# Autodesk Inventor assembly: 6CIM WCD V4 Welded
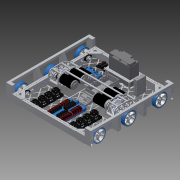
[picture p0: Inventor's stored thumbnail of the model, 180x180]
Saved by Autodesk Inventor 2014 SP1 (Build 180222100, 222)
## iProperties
Created: 2014-09
Part Number: 6CIM WCD V4 Welded
Document SubType Name: Assembly
Designer: Michael
Mass: 17694.5 g
Surface Area: 46905.3 cm^2
Volume: 10866 cm^3
Density: 1.62843 g/cm^3
Author: Michael
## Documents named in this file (25)
- C:\Users\Michael\Documents\Inventor\6 CIM in Line\6CIM WCD V4 Welded.iam
- C:\Users\Michael\Documents\Inventor\6 CIM V2\Base Plate.ipt
- C:\Users\Michael\Documents\Inventor\6 CIM V2\Side Rail.ipt
- C:\Users\Michael\Documents\Inventor\6 CIM V2\Front and Back Rail.ipt
- C:\Users\Michael\Documents\Inventor\6 CIM V2\Wheel-Bearing Block-Sprocket Sub.iam
- C:\Users\Michael\Documents\Inventor\6 CIM V2\Middle Wheel-Bearing Block.iam
- C:\Users\Michael\Documents\Inventor\6 CIM V2\217-3431-STEP.ipt
- C:\Users\Michael\Documents\Inventor\6 CIM V2\Battery Box.ipt
- C:\Users\Michael\Documents\Inventor\6 CIM V2\CS_Controller_217-2769.ipt
- C:\Users\Michael\Documents\Inventor\6 CIM V2\CS_PowerBoard_A003206.ipt
- C:\Users\Michael\Documents\Inventor\Bicycle\Imported Components\cd_crio-9074\cd_crio-9074.ipt
- C:\Users\Michael\Documents\Inventor\6 CIM V2\CS_SideCar_A003333.ipt
- C:\Users\Michael\Documents\Inventor\6 CIM V2\Breaker.iam
- C:\Users\Michael\Documents\Inventor\6 CIM V2\EK_6_Port_Manifold.ipt
- C:\Users\Michael\Documents\Inventor\6 CIM V2\battery.ipt
- C:\Users\Michael\Documents\Inventor\6 CIM V2\Battery Box Standoff.ipt
- C:\Users\Michael\Documents\Inventor\6 CIM V2\Gearbox Connecting Standoff.ipt
- C:\Users\Michael\Documents\Inventor\6 CIM in Line\6 CIM in Line Gearbox Ratio 2.iam
- C:\Users\Michael\Documents\Inventor\6 CIM in Line\6 CIM in Line Gearbox Ratio 2 MIR.ipt
- C:\Users\Michael\Documents\Inventor\6CIM\Wheel Well Frame Block.ipt
- C:\Users\Michael\Documents\Inventor\6CIM\Frame Mounting Bar.ipt
- C:\Users\Michael\Documents\Inventor\6CIM\Frame Mounting Corner.ipt
- C:\Users\Michael\Documents\Inventor\6CIM\Frame Mounting Corner Cap.ipt
- C:\Users\Michael\Documents\Inventor\6CIM\Wheel Well Frame Block Cap.ipt
- C:\Users\Michael\Documents\Inventor\6 CIM V2\Gusset.ipt
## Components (58 placed, 24 different names)
1. Base Plate:1 — Mate:1, Mate:2, Mate:3, Mate:4, Mate:5, Mate:6, Mate:8, Mate:9, Mate:10, Mate:11, Mate:71, Mate:75, Mate:76, Mate:92, Mate:94, Mate:97, Mate:99, Mate:106, Mate:119, Mate:152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
2. Side Rail:1 — Mate:1, Flush:1, Mate:2, Mate:3, Mate:27, Mate:28, Mate:29, Mate:30, Mate:31, Mate:32, Mate:33, Mate:34, Mate:35, Mate:45, Mate:46, Mate:47, Mate:48, Mate:79, Angle:1, Mate:111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
3. Side Rail:2 — Flush:1, Mate:4, Mate:5, Mate:7, Mate:21, Mate:22, Mate:23, Mate:24, Mate:25, Mate:26, Mate:36, Mate:37, Mate:38, Mate:43, Mate:44, Mate:49, Mate:50, Angle:2, Mate:102, Mate:153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
4. Front and Back Rail:1 — Mate:9, Mate:10, Mate:11, Mate:70, Mate:74, Mate:112, Mate:172, Mate:175, Mate:178, Mate:181, Flush:97, Flush:98, Mate:182, Flush:99, Flush:100, Mate:197, Flush:116, Mate:198, Flush:117
5. Front and Back Rail:2 — Mate:6, Mate:7, Mate:8, Mate:83, Mate:95, Mate:171, Mate:176, Mate:179, Flush:91, Flush:92, Flush:93, Flush:94, Mate:180, Flush:95, Flush:96, Mate:196, Flush:113, Mate:199, Flush:119
6. Wheel-Bearing Block-Sprocket Sub:1 [sub-assembly] — Mate:27, Mate:28, Mate:29
7. Wheel-Bearing Block-Sprocket Sub:2 [sub-assembly] — Mate:30, Mate:31, Mate:32
8. Wheel-Bearing Block-Sprocket Sub:3 [sub-assembly] — Mate:21, Mate:22, Mate:23
9. Wheel-Bearing Block-Sprocket Sub:4 [sub-assembly] — Mate:24, Mate:25, Mate:26
10. Middle Wheel-Bearing Block:1 [sub-assembly] — Mate:33, Mate:34, Mate:35
11. Middle Wheel-Bearing Block:2 [sub-assembly] — Mate:36, Mate:37, Mate:38, Tangent:1, Tangent:2
12. 217-3431-STEP:1 — Mate:44, Mate:49
13. 217-3431-STEP:2 — Mate:45, Mate:48
14. 217-3431-STEP:3 — Mate:43, Mate:50
15. 217-3431-STEP:4 — Mate:46, Mate:47
16. Battery Box:1 — Mate:70, Flush:14, Mate:74, Mate:105, Mate:108, Mate:110, Mate:151, Mate:167, Mate:168
17. CS_Controller_217-2769:1 — Mate:75, Mate:79, Flush:15, Flush:18, Mate:80, Mate:83, Flush:82
18. CS_Controller_217-2769:2 — Mate:76, Flush:21, Flush:79
19. CS_Controller_217-2769:3 — Flush:15, Flush:16, Flush:18, Flush:19, Mate:80, Mate:81, Flush:81
20. CS_Controller_217-2769:4 — Flush:16, Flush:17, Flush:19, Flush:20, Mate:81, Mate:82, Flush:80
21. CS_Controller_217-2769:5 — Flush:17, Flush:20, Mate:82, Flush:79
22. CS_Controller_217-2769:6 — Flush:21, Flush:22, Flush:80
23. CS_Controller_217-2769:7 — Flush:22, Flush:23, Flush:81
24. CS_Controller_217-2769:8 — Flush:23, Flush:82
25. CS_PowerBoard_A003206:1 — Mate:92, Angle:1, Mate:93, Mate:95
26. cd_crio-9074:1 — Mate:94, Flush:24, Mate:166
27. CS_SideCar_A003333:1 — Mate:97, Mate:156
28. Breaker:1 [sub-assembly] — Mate:99, Angle:2, Mate:102, Mate:164
29. EK_6_Port_Manifold:1 — Mate:106, Mate:111, Mate:112
30. battery:1 — Mate:105, Mate:151, Mate:152
31. Battery Box Standoff:1 — Mate:108, Mate:168
32. Battery Box Standoff:4 — Mate:110, Mate:167
33. Gearbox Connecting Standoff:1 — Mate:162, Mate:163
34. Gearbox Connecting Standoff:2 — Mate:160, Mate:161
35. 6 CIM in Line Gearbox Ratio 2:1 [sub-assembly] — Mate:153, Mate:154, Mate:155, Mate:161, Mate:162, Mate:163
36. 6 CIM in Line Gearbox Ratio 2 MIR:1 — Mate:157, Mate:158, Mate:159, Mate:160
37. Wheel Well Frame Block:1 — Flush:84, Mate:170, Mate:171, Mate:190, Flush:110
38. Wheel Well Frame Block:2 — Mate:169, Flush:83, Mate:172, Flush:90, Mate:188, Flush:109
39. Wheel Well Frame Block:3 — Flush:86, Mate:174, Mate:176, Flush:111
40. Wheel Well Frame Block:4 — Mate:173, Flush:85, Mate:175, Flush:87, Mate:194, Flush:112
41. Frame Mounting Bar:1 — Flush:87, Mate:178, Flush:88, Flush:89, Flush:108, Mate:193, Mate:195
42. Frame Mounting Bar:2 — Flush:88, Flush:89, Flush:90, Mate:184, Mate:189, Mate:191
43. Frame Mounting Corner:1 — Mate:182, Flush:99, Flush:100, Mate:187, Flush:106, Flush:107
44. Frame Mounting Corner:2 — Mate:179, Flush:91, Flush:92, Flush:93, Flush:94, Mate:186, Flush:104, Flush:105
45. Frame Mounting Corner:3 — Mate:180, Flush:95, Flush:96, Mate:185, Flush:102, Flush:103
46. Frame Mounting Corner:4 — Mate:181, Flush:97, Flush:98, Mate:183, Flush:101
47. Frame Mounting Corner Cap:1 — Mate:183, Mate:184, Flush:101
48. Frame Mounting Corner Cap:2 — Mate:187, Flush:106, Flush:107, Flush:108
49. Frame Mounting Corner Cap:3 — Mate:185, Flush:102, Flush:103
50. Frame Mounting Corner Cap:4 — Mate:186, Flush:104, Flush:105
51. Wheel Well Frame Block Cap:1 — Mate:190, Mate:191, Flush:110
52. Wheel Well Frame Block Cap:2 — Mate:194, Mate:195, Flush:112
53. Wheel Well Frame Block Cap:3 — Mate:188, Mate:189, Flush:109
54. Wheel Well Frame Block Cap:4 — Mate:192, Mate:193, Flush:111
55. Gusset:1 — Mate:199, Flush:119, Flush:120
56. Gusset:2 — Mate:197, Flush:115, Flush:116
57. Gusset:3 — Mate:196, Flush:113, Flush:114
58. Gusset:4 — Mate:198, Flush:117, Flush:118
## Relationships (167: Mate 108, Flush 54, Angle 3, Tangent 2)
- Mate:1: Base Plate:1 ↔ Side Rail:1
- Flush:1: Side Rail:1 ↔ Side Rail:2
- Mate:2: Base Plate:1 ↔ Side Rail:1
- Mate:3: Base Plate:1 ↔ Side Rail:1
- Mate:4: Base Plate:1 ↔ Side Rail:2
- Mate:5: Base Plate:1 ↔ Side Rail:2
- Mate:6: Base Plate:1 ↔ Front and Back Rail:2
- Mate:7: Side Rail:2 ↔ Front and Back Rail:2
- Mate:8: Base Plate:1 ↔ Front and Back Rail:2
- Mate:9: Base Plate:1 ↔ Front and Back Rail:1
- Mate:10: Base Plate:1 ↔ Front and Back Rail:1
- Mate:11: Base Plate:1 ↔ Front and Back Rail:1
- Mate:21: Side Rail:2 ↔ Wheel-Bearing Block-Sprocket Sub:3
- Mate:22: Side Rail:2 ↔ Wheel-Bearing Block-Sprocket Sub:3
- Mate:23: Side Rail:2 ↔ Wheel-Bearing Block-Sprocket Sub:3
- Mate:24: Side Rail:2 ↔ Wheel-Bearing Block-Sprocket Sub:4
- Mate:25: Side Rail:2 ↔ Wheel-Bearing Block-Sprocket Sub:4
- Mate:26: Side Rail:2 ↔ Wheel-Bearing Block-Sprocket Sub:4
- Mate:27: Side Rail:1 ↔ Wheel-Bearing Block-Sprocket Sub:1
- Mate:28: Side Rail:1 ↔ Wheel-Bearing Block-Sprocket Sub:1
- Mate:29: Side Rail:1 ↔ Wheel-Bearing Block-Sprocket Sub:1
- Mate:30: Side Rail:1 ↔ Wheel-Bearing Block-Sprocket Sub:2
- Mate:31: Side Rail:1 ↔ Wheel-Bearing Block-Sprocket Sub:2
- Mate:32: Side Rail:1 ↔ Wheel-Bearing Block-Sprocket Sub:2
- Mate:33: Side Rail:1 ↔ Middle Wheel-Bearing Block:1
- Mate:34: Side Rail:1 ↔ Middle Wheel-Bearing Block:1
- Mate:35: Side Rail:1 ↔ Middle Wheel-Bearing Block:1
- Mate:36: Side Rail:2 ↔ Middle Wheel-Bearing Block:2
- Mate:37: Side Rail:2 ↔ Middle Wheel-Bearing Block:2
- Mate:38: Side Rail:2 ↔ Middle Wheel-Bearing Block:2
- Mate:43: Side Rail:2 ↔ 217-3431-STEP:3
- Mate:44: Side Rail:2 ↔ 217-3431-STEP:1
- Mate:45: Side Rail:1 ↔ 217-3431-STEP:2
- Mate:46: Side Rail:1 ↔ 217-3431-STEP:4
- Mate:47: Side Rail:1 ↔ 217-3431-STEP:4
- Mate:48: Side Rail:1 ↔ 217-3431-STEP:2
- Mate:49: Side Rail:2 ↔ 217-3431-STEP:1
- Mate:50: Side Rail:2 ↔ 217-3431-STEP:3
- Mate:70: Front and Back Rail:1 ↔ Battery Box:1
- Mate:71: Base Plate:1
- Flush:14: Battery Box:1
- Mate:74: Front and Back Rail:1 ↔ Battery Box:1
- Mate:75: Base Plate:1 ↔ CS_Controller_217-2769:1
- Mate:76: Base Plate:1 ↔ CS_Controller_217-2769:2
- Mate:79: Side Rail:1 ↔ CS_Controller_217-2769:1
- Flush:15: CS_Controller_217-2769:1 ↔ CS_Controller_217-2769:3
- Flush:16: CS_Controller_217-2769:3 ↔ CS_Controller_217-2769:4
- Flush:17: CS_Controller_217-2769:4 ↔ CS_Controller_217-2769:5
- Flush:18: CS_Controller_217-2769:1 ↔ CS_Controller_217-2769:3
- Flush:19: CS_Controller_217-2769:3 ↔ CS_Controller_217-2769:4
- Flush:20: CS_Controller_217-2769:4 ↔ CS_Controller_217-2769:5
- Mate:80: CS_Controller_217-2769:1 ↔ CS_Controller_217-2769:3
- Mate:81: CS_Controller_217-2769:3 ↔ CS_Controller_217-2769:4
- Mate:82: CS_Controller_217-2769:4 ↔ CS_Controller_217-2769:5
- Mate:83: Front and Back Rail:2 ↔ CS_Controller_217-2769:1
- Flush:21: CS_Controller_217-2769:2 ↔ CS_Controller_217-2769:6
- Flush:22: CS_Controller_217-2769:6 ↔ CS_Controller_217-2769:7
- Flush:23: CS_Controller_217-2769:7 ↔ CS_Controller_217-2769:8
- Mate:92: Base Plate:1 ↔ CS_PowerBoard_A003206:1
- Angle:1: Side Rail:1 ↔ CS_PowerBoard_A003206:1
- Mate:93: CS_PowerBoard_A003206:1
- Mate:94: Base Plate:1 ↔ cd_crio-9074:1
- Flush:24: cd_crio-9074:1
- Mate:95: Front and Back Rail:2 ↔ CS_PowerBoard_A003206:1
- Mate:97: Base Plate:1 ↔ CS_SideCar_A003333:1
- Mate:99: Base Plate:1 ↔ Breaker:1
- Angle:2: Side Rail:2 ↔ Breaker:1
- Mate:102: Side Rail:2 ↔ Breaker:1
- Mate:105: Battery Box:1 ↔ battery:1
- Mate:106: Base Plate:1 ↔ EK_6_Port_Manifold:1
- Mate:108: Battery Box:1 ↔ Battery Box Standoff:1
- Mate:110: Battery Box:1 ↔ Battery Box Standoff:4
- Mate:111: Side Rail:1 ↔ EK_6_Port_Manifold:1
- Mate:112: Front and Back Rail:1 ↔ EK_6_Port_Manifold:1
- Tangent:1: Middle Wheel-Bearing Block:2
- Mate:119: Base Plate:1
- Mate:151: Battery Box:1 ↔ battery:1
- Mate:152: Base Plate:1 ↔ battery:1
- Mate:153: Side Rail:2 ↔ 6 CIM in Line Gearbox Ratio 2:1
- Mate:154: Side Rail:2 ↔ 6 CIM in Line Gearbox Ratio 2:1
- Mate:155: Side Rail:2 ↔ 6 CIM in Line Gearbox Ratio 2:1
- Mate:156: Base Plate:1 ↔ CS_SideCar_A003333:1
- Mate:157: Side Rail:1 ↔ 6 CIM in Line Gearbox Ratio 2 MIR:1
- Mate:158: Side Rail:1 ↔ 6 CIM in Line Gearbox Ratio 2 MIR:1
- Mate:159: Side Rail:1 ↔ 6 CIM in Line Gearbox Ratio 2 MIR:1
- Mate:160: Gearbox Connecting Standoff:2 ↔ 6 CIM in Line Gearbox Ratio 2 MIR:1
- Mate:161: Gearbox Connecting Standoff:2 ↔ 6 CIM in Line Gearbox Ratio 2:1
- Mate:162: Gearbox Connecting Standoff:1 ↔ 6 CIM in Line Gearbox Ratio 2:1
- Mate:163: Gearbox Connecting Standoff:1 ↔ 6 CIM in Line Gearbox Ratio 2:1
- Angle:4: Side Rail:2
- Tangent:2: Middle Wheel-Bearing Block:2
- Mate:164: Base Plate:1 ↔ Breaker:1
- Mate:166: Base Plate:1 ↔ cd_crio-9074:1
- Mate:167: Battery Box:1 ↔ Battery Box Standoff:4
- Mate:168: Battery Box:1 ↔ Battery Box Standoff:1
- Flush:79: CS_Controller_217-2769:2 ↔ CS_Controller_217-2769:5
- Flush:80: CS_Controller_217-2769:4 ↔ CS_Controller_217-2769:6
- Flush:81: CS_Controller_217-2769:3 ↔ CS_Controller_217-2769:7
- Flush:82: CS_Controller_217-2769:1 ↔ CS_Controller_217-2769:8
- Mate:169: Side Rail:2 ↔ Wheel Well Frame Block:2
- Flush:83: Side Rail:2 ↔ Wheel Well Frame Block:2
- Flush:84: Side Rail:2 ↔ Wheel Well Frame Block:1
- Mate:170: Side Rail:2 ↔ Wheel Well Frame Block:1
- Mate:171: Front and Back Rail:2 ↔ Wheel Well Frame Block:1
- Mate:172: Front and Back Rail:1 ↔ Wheel Well Frame Block:2
- Mate:173: Side Rail:1 ↔ Wheel Well Frame Block:4
- Flush:85: Side Rail:1 ↔ Wheel Well Frame Block:4
- Flush:86: Side Rail:1 ↔ Wheel Well Frame Block:3
- Mate:174: Side Rail:1 ↔ Wheel Well Frame Block:3
- Mate:175: Front and Back Rail:1 ↔ Wheel Well Frame Block:4
- Mate:176: Front and Back Rail:2 ↔ Wheel Well Frame Block:3
- Flush:87: Wheel Well Frame Block:4 ↔ Frame Mounting Bar:1
- Mate:178: Front and Back Rail:1 ↔ Frame Mounting Bar:1
- Flush:88: Frame Mounting Bar:1 ↔ Frame Mounting Bar:2
- Flush:89: Frame Mounting Bar:1 ↔ Frame Mounting Bar:2
- Flush:90: Wheel Well Frame Block:2 ↔ Frame Mounting Bar:2
- Mate:179: Front and Back Rail:2 ↔ Frame Mounting Corner:2
- Flush:91: Front and Back Rail:2 ↔ Frame Mounting Corner:2
- Flush:92: Front and Back Rail:2 ↔ Frame Mounting Corner:2
- Flush:93: Front and Back Rail:2 ↔ Frame Mounting Corner:2
- Flush:94: Front and Back Rail:2 ↔ Frame Mounting Corner:2
- Mate:180: Front and Back Rail:2 ↔ Frame Mounting Corner:3
- Flush:95: Front and Back Rail:2 ↔ Frame Mounting Corner:3
- Flush:96: Front and Back Rail:2 ↔ Frame Mounting Corner:3
- Mate:181: Front and Back Rail:1 ↔ Frame Mounting Corner:4
- Flush:97: Front and Back Rail:1 ↔ Frame Mounting Corner:4
- Flush:98: Front and Back Rail:1 ↔ Frame Mounting Corner:4
- Mate:182: Front and Back Rail:1 ↔ Frame Mounting Corner:1
- Flush:99: Front and Back Rail:1 ↔ Frame Mounting Corner:1
- Flush:100: Front and Back Rail:1 ↔ Frame Mounting Corner:1
- Mate:183: Frame Mounting Corner:4 ↔ Frame Mounting Corner Cap:1
- Mate:184: Frame Mounting Bar:2 ↔ Frame Mounting Corner Cap:1
- Flush:101: Frame Mounting Corner:4 ↔ Frame Mounting Corner Cap:1
- Mate:185: Frame Mounting Corner:3 ↔ Frame Mounting Corner Cap:3
- Flush:102: Frame Mounting Corner:3 ↔ Frame Mounting Corner Cap:3
- Flush:103: Frame Mounting Corner:3 ↔ Frame Mounting Corner Cap:3
- Mate:186: Frame Mounting Corner:2 ↔ Frame Mounting Corner Cap:4
- Flush:104: Frame Mounting Corner:2 ↔ Frame Mounting Corner Cap:4
- Flush:105: Frame Mounting Corner:2 ↔ Frame Mounting Corner Cap:4
- Mate:187: Frame Mounting Corner:1 ↔ Frame Mounting Corner Cap:2
- Flush:106: Frame Mounting Corner:1 ↔ Frame Mounting Corner Cap:2
- Flush:107: Frame Mounting Corner:1 ↔ Frame Mounting Corner Cap:2
- Flush:108: Frame Mounting Bar:1 ↔ Frame Mounting Corner Cap:2
- Mate:188: Wheel Well Frame Block:2 ↔ Wheel Well Frame Block Cap:3
- Mate:189: Frame Mounting Bar:2 ↔ Wheel Well Frame Block Cap:3
- Flush:109: Wheel Well Frame Block:2 ↔ Wheel Well Frame Block Cap:3
- Mate:190: Wheel Well Frame Block:1 ↔ Wheel Well Frame Block Cap:1
- Mate:191: Frame Mounting Bar:2 ↔ Wheel Well Frame Block Cap:1
- Flush:110: Wheel Well Frame Block:1 ↔ Wheel Well Frame Block Cap:1
- Mate:192: Side Rail:1 ↔ Wheel Well Frame Block Cap:4
- Mate:193: Frame Mounting Bar:1 ↔ Wheel Well Frame Block Cap:4
- Flush:111: Wheel Well Frame Block:3 ↔ Wheel Well Frame Block Cap:4
- Mate:194: Wheel Well Frame Block:4 ↔ Wheel Well Frame Block Cap:2
- Mate:195: Frame Mounting Bar:1 ↔ Wheel Well Frame Block Cap:2
- Flush:112: Wheel Well Frame Block:4 ↔ Wheel Well Frame Block Cap:2
- Mate:196: Front and Back Rail:2 ↔ Gusset:3
- Flush:113: Front and Back Rail:2 ↔ Gusset:3
- Flush:114: Side Rail:2 ↔ Gusset:3
- Mate:197: Front and Back Rail:1 ↔ Gusset:2
- Flush:115: Side Rail:2 ↔ Gusset:2
- Flush:116: Front and Back Rail:1 ↔ Gusset:2
- Mate:198: Front and Back Rail:1 ↔ Gusset:4
- Flush:117: Front and Back Rail:1 ↔ Gusset:4
- Flush:118: Side Rail:1 ↔ Gusset:4
- Mate:199: Front and Back Rail:2 ↔ Gusset:1
- Flush:119: Front and Back Rail:2 ↔ Gusset:1
- Flush:120: Side Rail:1 ↔ Gusset:1
